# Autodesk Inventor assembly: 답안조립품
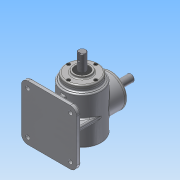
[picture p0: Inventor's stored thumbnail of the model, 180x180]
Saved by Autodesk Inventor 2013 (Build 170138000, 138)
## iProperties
Created: 2015-07
Part Number: 답안조립품
Document SubType Name: Assembly
Designer: Administrator
Author: Administrator
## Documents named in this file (14)
- C:\Users\Administrator\Desktop\450706V1024\답안조립품.iam
- C:\Users\Administrator\Desktop\450706V1024\본체.ipt
- C:\Users\Administrator\Desktop\450706V1024\M4.ipt
- C:\Users\Administrator\Desktop\450706V1024\메인 베벨기어.ipt
- C:\Users\Administrator\Desktop\450706V1024\메인 축.ipt
- 메인 축.ipt
- C:\Users\Administrator\Desktop\450706V1024\베어링 6203.ipt
- C:\Users\Administrator\Desktop\450706V1024\서브 베벨기어.ipt
- C:\Users\Administrator\Desktop\450706V1024\서브 축.ipt
- 서브 축.ipt
- C:\Users\Administrator\Desktop\450706V1024\오일실.ipt
- C:\Users\Administrator\Desktop\450706V1024\커버.ipt
- C:\Users\Administrator\Desktop\450706V1024\키 4x4.ipt
- C:\Users\Administrator\Desktop\450706V1024\키 5x5.ipt
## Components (8 placed, 1 different names)
1. M4:1
2. M4:3
3. M4:4
4. M4:5
5. M4:2
6. M4:6
7. M4:7
8. M4:8
